(* Logix 5000 project; controller R21 vendor 1 type 14 code 96 rev 21.11; software revision 21.00; part 5 of 5 *)

ADD_ON_INSTRUCTION PSDNP3EventG40V03   (* revision 1.0, vendor ProSoft Technology Inc *)
VAR_IN_OUT
   EventBuffer : PSDNP3MasterEvent[1]; {required}
END_VAR
VAR_INPUT
   BufferSize : DINT; {required}
   CurrentBufferIndex : DINT; {required}
   Reset : BOOL; {required}
   OutstationNodeAddress : INT; {required}
   OutstationIPAddress0 : INT; {required}
   OutstationIPAddress1 : INT; {required}
   OutstationIPAddress2 : INT; {required}
   OutstationIPAddress3 : INT; {required}
END_VAR
VAR_IN_OUT
   DNP3StaticObject : PSDNP3AnalogOutputStatusRealFlag[1]; {required}
END_VAR
VAR_INPUT
   MaxtElementCount : DINT; {required}
END_VAR
VAR_OUTPUT
   EventsProcessed : DINT; {access Read Only, visible}
   LastElementIndex : DINT; {access Read Only, visible}
   LastValue : REAL; {access Read Only, visible}
   LastStatus : SINT; {access Read Only, visible}
   CurrentUnloadIndex : DINT; {access Read Only, visible}
END_VAR
VAR
   UnloadIndex : DINT; {access None}
   EnableInTemp : BOOL; {access None}
   InitialScan : BOOL; {access None}
   EntryValidForProcessing : BOOL; {access None}
   ElementIndex : DINT; {access None}
   NextIndex : DINT; {access None}
   ResetPulse : BOOL; {access None}
   ResetONS : BOOL; {access None}
END_VAR

ROUTINE Logic   (* ladder *)
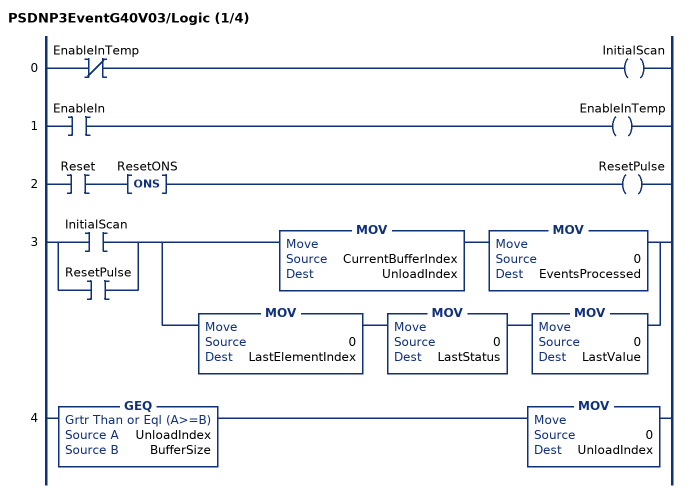
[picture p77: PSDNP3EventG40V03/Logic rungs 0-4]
   0: XIO(EnableInTemp)OTE(InitialScan);
   1: XIC(EnableIn)OTE(EnableInTemp);
   2: XIC(Reset)ONS(ResetONS)OTE(ResetPulse);
   3: [XIC(InitialScan) ,XIC(ResetPulse) ][MOV(CurrentBufferIndex,UnloadIndex) MOV(0,EventsProcessed) ,MOV(0,LastElementIndex) MOV(0,LastStatus) MOV(0,LastValue) ];
   4: GEQ(UnloadIndex,BufferSize)MOV(0,UnloadIndex);
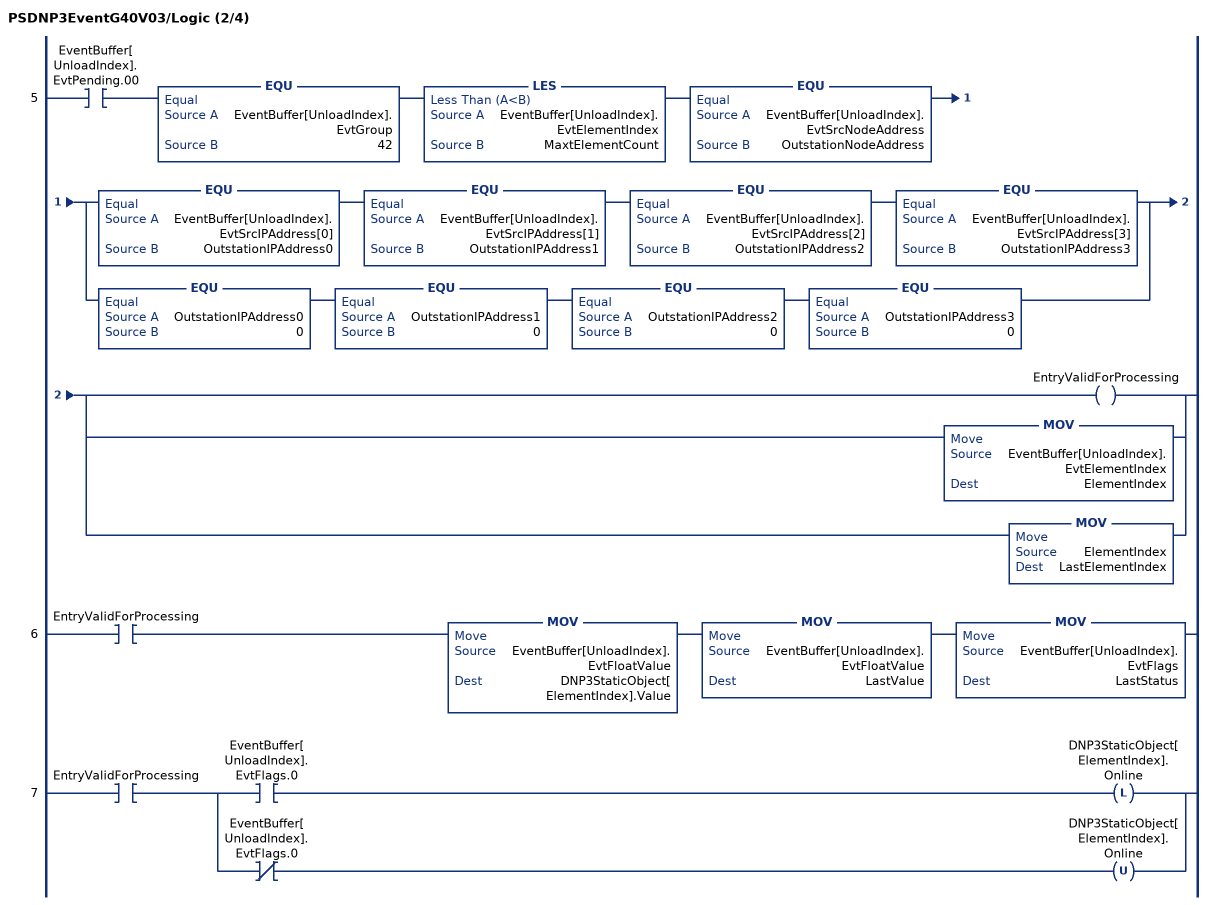
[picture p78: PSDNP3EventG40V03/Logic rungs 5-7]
   5: XIC(EventBuffer[UnloadIndex].EvtPending.00)EQU(EventBuffer[UnloadIndex].EvtGroup,42)LES(EventBuffer[UnloadIndex].EvtElementIndex,MaxtElementCount)EQU(EventBuffer[UnloadIndex].EvtSrcNodeAddress,OutstationNodeAddress)[EQU(EventBuffer[UnloadIndex].EvtSrcIPAddress[0],OutstationIPAddress0) EQU(EventBuffer[UnloadIndex].EvtSrcIPAddress[1],OutstationIPAddress1) EQU(EventBuffer[UnloadIndex].EvtSrcIPAddress[2],OutstationIPAddress2) EQU(EventBuffer[UnloadIndex].EvtSrcIPAddress[3],OutstationIPAddress3) ,EQU(OutstationIPAddress0,0) EQU(OutstationIPAddress1,0) EQU(OutstationIPAddress2,0) EQU(OutstationIPAddress3,0) ][OTE(EntryValidForProcessing) ,MOV(EventBuffer[UnloadIndex].EvtElementIndex,ElementIndex) ,MOV(ElementIndex,LastElementIndex) ];
   6: XIC(EntryValidForProcessing)MOV(EventBuffer[UnloadIndex].EvtFloatValue,DNP3StaticObject[ElementIndex].Value)MOV(EventBuffer[UnloadIndex].EvtFloatValue,LastValue)MOV(EventBuffer[UnloadIndex].EvtFlags,LastStatus);
   7: XIC(EntryValidForProcessing)[XIC(EventBuffer[UnloadIndex].EvtFlags.0) OTL(DNP3StaticObject[ElementIndex].Online) ,XIO(EventBuffer[UnloadIndex].EvtFlags.0) OTU(DNP3StaticObject[ElementIndex].Online) ];
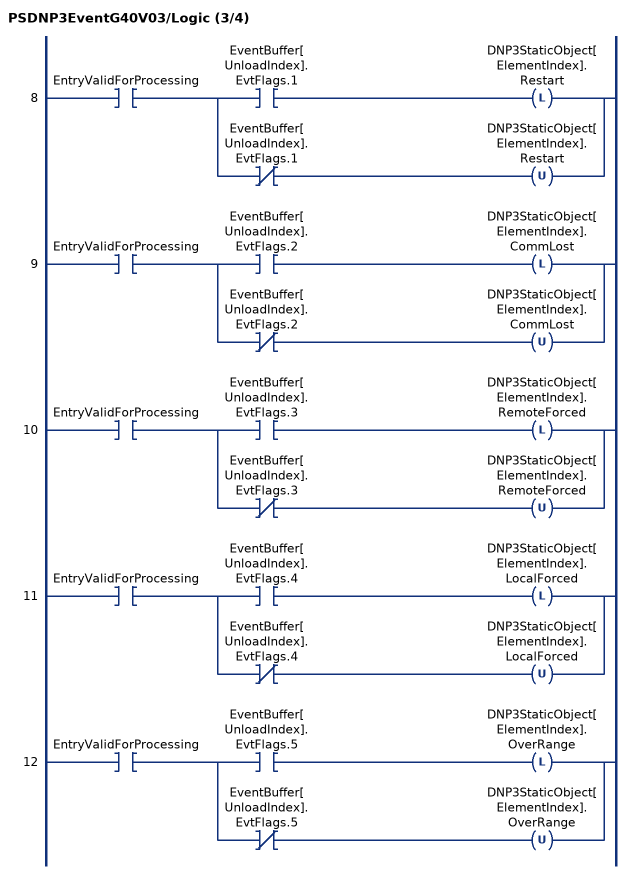
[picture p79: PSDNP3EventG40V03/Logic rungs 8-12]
   8: XIC(EntryValidForProcessing)[XIC(EventBuffer[UnloadIndex].EvtFlags.1) OTL(DNP3StaticObject[ElementIndex].Restart) ,XIO(EventBuffer[UnloadIndex].EvtFlags.1) OTU(DNP3StaticObject[ElementIndex].Restart) ];
   9: XIC(EntryValidForProcessing)[XIC(EventBuffer[UnloadIndex].EvtFlags.2) OTL(DNP3StaticObject[ElementIndex].CommLost) ,XIO(EventBuffer[UnloadIndex].EvtFlags.2) OTU(DNP3StaticObject[ElementIndex].CommLost) ];
   10: XIC(EntryValidForProcessing)[XIC(EventBuffer[UnloadIndex].EvtFlags.3) OTL(DNP3StaticObject[ElementIndex].RemoteForced) ,XIO(EventBuffer[UnloadIndex].EvtFlags.3) OTU(DNP3StaticObject[ElementIndex].RemoteForced) ];
   11: XIC(EntryValidForProcessing)[XIC(EventBuffer[UnloadIndex].EvtFlags.4) OTL(DNP3StaticObject[ElementIndex].LocalForced) ,XIO(EventBuffer[UnloadIndex].EvtFlags.4) OTU(DNP3StaticObject[ElementIndex].LocalForced) ];
   12: XIC(EntryValidForProcessing)[XIC(EventBuffer[UnloadIndex].EvtFlags.5) OTL(DNP3StaticObject[ElementIndex].OverRange) ,XIO(EventBuffer[UnloadIndex].EvtFlags.5) OTU(DNP3StaticObject[ElementIndex].OverRange) ];
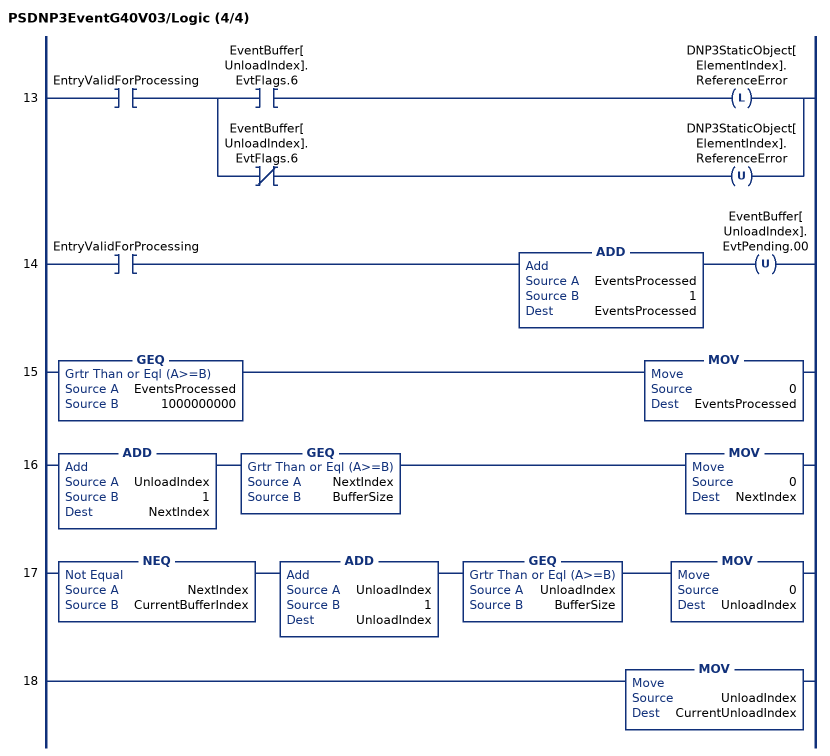
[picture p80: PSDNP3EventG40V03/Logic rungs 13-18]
   13: XIC(EntryValidForProcessing)[XIC(EventBuffer[UnloadIndex].EvtFlags.6) OTL(DNP3StaticObject[ElementIndex].ReferenceError) ,XIO(EventBuffer[UnloadIndex].EvtFlags.6) OTU(DNP3StaticObject[ElementIndex].ReferenceError) ];
   14: XIC(EntryValidForProcessing)ADD(EventsProcessed,1,EventsProcessed)OTU(EventBuffer[UnloadIndex].EvtPending.00);
   15: GEQ(EventsProcessed,1000000000)MOV(0,EventsProcessed);
   16: ADD(UnloadIndex,1,NextIndex)GEQ(NextIndex,BufferSize)MOV(0,NextIndex);
   17: NEQ(NextIndex,CurrentBufferIndex)ADD(UnloadIndex,1,UnloadIndex)GEQ(UnloadIndex,BufferSize)MOV(0,UnloadIndex);
   18: MOV(UnloadIndex,CurrentUnloadIndex);
END_ROUTINE
END_ADD_ON_INSTRUCTION

VAR_GLOBAL   (* controller tags *)
   DNP3G01V01 : PSDNP3BinaryInputPacked[10] := ([0].BinaryValues[0] := 9, [0].BinaryValues[1] := 1, [0].BinaryValues[2] := 1, [0].BinaryValues[3] := -64);
   DNP3G01V02 : PSDNP3BinaryInputWithFlag[100];
   DNP3G01V02_RBE : PSDNP3EventG01V02 := (BufferSize := 100, CurrentBufferIndex := 10, Reset := 1, OutstationNodeAddress := 2, MaxtElementCount := 10, EventsProcessed := 3, LastStatus := 81, CurrentUnloadIndex := 9);
   DNP3G03V01 : PSDNP3DoubleBinaryInputPacked[10];
   DNP3G03V02 : PSDNP3DoubleBinaryInputWithFlag[10] := ([0].Online := 1, [0].LocalForced := 1, [0].State0 := 1, [0].State1 := 1, [1].State1 := 1, [9].Online := 1, [9].CommLost := 1, [9].LocalForced := 1, [9].State0 := 1);
   DNP3G03V02_RBE : PSDNP3EventG03V02 := (BufferSize := 100, CurrentBufferIndex := 10, Reset := 1, OutstationNodeAddress := 2, MaxtElementCount := 10, EventsProcessed := 6, LastElementIndex := 1, LastValue := 2, CurrentUnloadIndex := 9);
   DNP3G10V0 : PSDNP3BinaryOutputWithFlag[10] := ([0].Online := 1, [0].CommLost := 1, [0].LocalForced := 1, [0].Reserved2 := 1, [2].Online := 1, [2].State := 1);
   DNP3G10V01 : PSDNP3BinaryOutputPacked[10];
   DNP3G10V02 : PSDNP3BinaryOutputWithFlag[10] := ([0].Online := 1, [0].LocalForced := 1, [0].Reserved2 := 1, [0].State := 1, [1].Online := 1, [1].Restart := 1, [9].Online := 1, [9].CommLost := 1, [9].LocalForced := 1);
   DNP3G10V02_RBE : PSDNP3EventG10V02 := (BufferSize := 100, CurrentBufferIndex := 10, Reset := 1, OutstationNodeAddress := 2, MaxtElementCount := 10, EventsProcessed := 5, LastValue := 1, LastStatus := 81, CurrentUnloadIndex := 9);
   DNP3G110V01 : STRING[5];
   DNP3G12V01 : PSDNP3CROB[10] := ([0].ControlCode := 4, [0].Count := 5, [0].OnTime := 200, [0].OffTime := 380, [3].RequestPending := 1, [3].ControlCode := 3, [3].Count := 1, [3].OnTime := 100, [3].OffTime := 100);
   DNP3G1V0 : PSDNP3BinaryInputWithFlag[10] := ([0].Online := 1, [0].LocalForced := 1, [0].State := 1, [1].Online := 1, [2].Online := 1, [2].Restart := 1, [2].CommLost := 1, [4].Online := 1, [4].Restart := 1, [4].CommLost := 1, [4].RemoteForced := 1, [4].LocalForced := 1, [5].State := 1, [7].State := 1, [8].State := 1, [9].State := 1);
   DNP3G20_Freeze : PSDNP3FreezeCmd[10];
   DNP3G20V0 : PSDNP3Counter32WithFlag[10];
   DNP3G20V01 : PSDNP3Counter32WithFlag[10];
   DNP3G20V01_RBE : PSDNP3EventG20V01 := (BufferSize := 100, CurrentBufferIndex := 10, Reset := 1, OutstationNodeAddress := 2, MaxtElementCount := 10, EventsProcessed := 2, LastValue := 17, LastStatus := 19, CurrentUnloadIndex := 9);
   DNP3G20V02 : PSDNP3Counter16WithFlag[10];
   DNP3G20V05 : DINT[10] := ([0] := 143, [1] := 144, [2] := 145, [3] := 146, [4] := 147, [5] := 148, [6] := 149, [7] := 150, [8] := 151, [9] := 3456);
   DNP3G20V06 : INT[10] := ([0] := 6, [1] := 154, [2] := 155, [3] := 156, [4] := 157, [5] := 158, [6] := 159, [7] := 160, [8] := 161, [9] := 3456);
   DNP3G21V0 : PSDNP3FrozenCounter32WithFlagTime[10];
   DNP3G21V01 : PSDNP3FrozenCounter32WithFlag[10] := ([0].LocalForced := 1, [0].Value := 88, [1].Online := 1, [1].Value := 324, [2].Restart := 1, [2].CommLost := 1, [2].Value := 100268, [9].Online := 1, [9].CommLost := 1, [9].LocalForced := 1, [9].Discontinuity := 1, [9].Value := 3456);
   DNP3G21V01_RBE : PSDNP3EventG21V01 := (BufferSize := 100, CurrentBufferIndex := 10, Reset := 1, OutstationNodeAddress := 2, MaxtElementCount := 10, EventsProcessed := 10, LastValue := 88, LastStatus := 16, CurrentUnloadIndex := 9);
   DNP3G21V02 : PSDNP3FrozenCounter16WithFlag[10] := ([0].Online := 1, [0].Value := 32000, [5].Restart := 1, [5].CommLost := 1, [5].Value := 31000, [9].Online := 1, [9].CommLost := 1, [9].LocalForced := 1, [9].Discontinuity := 1, [9].Value := 3456);
   DNP3G21V05 : PSDNP3FrozenCounter32WithFlagTime[100];
   DNP3G21V05_RBE : PSDNP3EventG21V05 := (BufferSize := 100, CurrentBufferIndex := 13, Reset := 1, OutstationNodeAddress := 2, MaxtElementCount := 10, EventsProcessed := 73, LastValue := 77, LastStatus := 16, CurrentUnloadIndex := 12);
   DNP3G21V06 : PSDNP3FrozenCounter16WithFlagTime[10] := ([0].Online := 1, [0].Value := 3, [9].Online := 1, [9].CommLost := 1, [9].LocalForced := 1, [9].Discontinuity := 1, [9].Value := 3456, [9].TimeOfOccurrence := 1484716130000200);
   DNP3G21V09 : DINT[10] := ([9] := 3456);
   DNP3G21V10 : INT[10] := ([0] := 6, [9] := 3456);
   DNP3G30_Freeze : PSDNP3FreezeCmd[10];
   DNP3G30V0 : PSDNP3AnalogInputVar0[10];
   DNP3G30V01 : PSDNP3AnalogInput32Flag[10];
   DNP3G30V02 : PSDNP3AnalogInput16Flag[10] := ([9].Online := 1, [9].Restart := 1, [9].CommLost := 1, [9].Value := 3456);
   DNP3G30V03 : DINT[10] := ([9] := 3456);
   DNP3G30V04 : INT[10] := ([9] := 3456);
   DNP3G30V05 : PSDNP3AnalogInputRealFlag[100];
   DNP3G30V05_RBE : PSDNP3EventG30V05 := (BufferSize := 100, CurrentBufferIndex := 10, Reset := 1, OutstationNodeAddress := 2, MaxtElementCount := 10, EventsProcessed := 2, LastValue := 345.0, LastStatus := 1, CurrentUnloadIndex := 9);
   DNP3G31V01 : PSDNP3FrozenAnalog32WithFlag[10];
   DNP3G31V02 : PSDNP3FrozenAnalog16WithFlag[10];
   DNP3G31V03 : PSDNP3FrozenAnalog32WithFlagTime[10];
   DNP3G31V04 : PSDNP3FrozenAnalog16WithFlagTime[10];
   DNP3G31V05 : DINT[10];
   DNP3G31V06 : INT[10];
   DNP3G31V07 : PSDNP3FrozenAnalogRealWithFlag[10];
   DNP3G3V0 : PSDNP3DoubleBinaryInputWithFlag[10];
   DNP3G40V0 : PSDNP3AnalogOutputVar0[10];
   DNP3G40V01 : PSDNP3AnalogOutputStatus32Flag[10] := ([0].Online := 1, [0].Value := 56, [9].Online := 1, [9].CommLost := 1, [9].LocalForced := 1, [9].ReferenceError := 1, [9].Value := 3456);
   DNP3G40V02 : PSDNP3AnalogOutputStatus16Flag[10] := ([0].Online := 1, [0].Value := 123, [9].Online := 1, [9].CommLost := 1, [9].LocalForced := 1, [9].ReferenceError := 1, [9].Value := 3456);
   DNP3G40V03 : PSDNP3AnalogOutputStatusRealFlag[10] := ([0].Online := 1, [0].Value := 66.0, [1].Online := 1, [1].Value := 760.0, [9].Online := 1, [9].CommLost := 1, [9].LocalForced := 1, [9].ReferenceError := 1, [9].Value := 71.25);
   DNP3G40V03_RBE : PSDNP3EventG40V03 := (BufferSize := 100, CurrentBufferIndex := 10, Reset := 1, OutstationNodeAddress := 2, MaxtElementCount := 10, EventsProcessed := 2, LastValue := 66.0, LastStatus := 1, CurrentUnloadIndex := 9);
   DNP3G41V01 : PSDNP3AnalogOutput32[10] := ([0].Value := 56, [7].RequestPending := 1, [7].Value := 77);
   DNP3G41V02 : PSDNP3AnalogOutput16[10] := ([0].Value := 123);
   DNP3G41V03 : PSDNP3AnalogOutputReal[10] := ([0].Value := 33.56);
   DNP3MasterEventBuffer : PSDNP3MasterEvent[100];
   DNP3MasterUnloadReset : BOOL := 1;
   DNP3Message : MESSAGE;
        MessageParameters(ServiceCode := 16#006a, LocalElement := DNP3MsgRequest, DestinationTag := DNP3MsgResponse, ...)
   DNP3MsgRequest : PSDNP3MsgRequest := (DestinationNode := 1, RequestDataSize := 5, IPAddress[0] := 192, IPAddress[1] := 168, IPAddress[2] := 1, IPAddress[3] := 210, Function := 1);
   DNP3MsgResponse : PSDNP3MsgResponse;
   DNPMessageTrigger : BOOL;
END_VAR

PROGRAM DNP3Events   (* main routine Main *)

ROUTINE FromOutstation_01   (* ladder *)
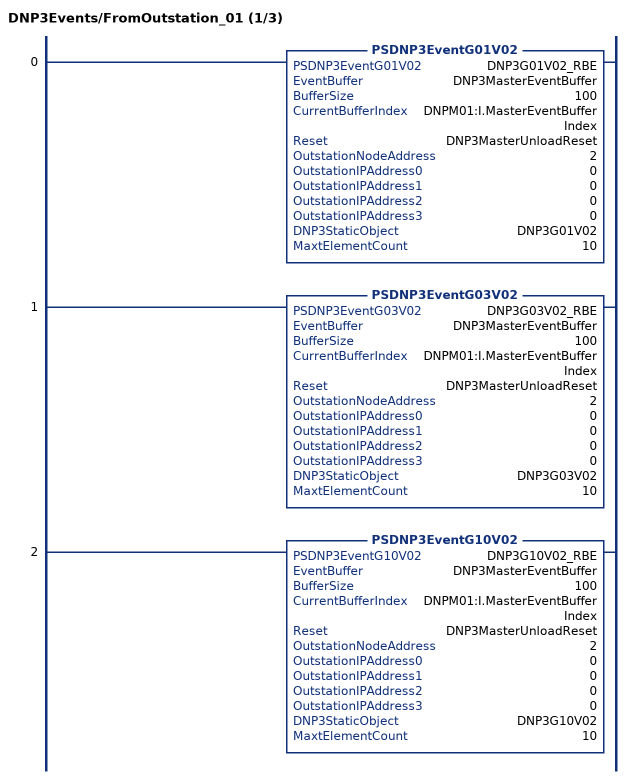
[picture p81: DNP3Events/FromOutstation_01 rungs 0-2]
   0: PSDNP3EventG01V02(DNP3G01V02_RBE,DNP3MasterEventBuffer,100,DNPM01:I.MasterEventBufferIndex,DNP3MasterUnloadReset,2,0,0,0,0,DNP3G01V02,10);
   1: PSDNP3EventG03V02(DNP3G03V02_RBE,DNP3MasterEventBuffer,100,DNPM01:I.MasterEventBufferIndex,DNP3MasterUnloadReset,2,0,0,0,0,DNP3G03V02,10);
   2: PSDNP3EventG10V02(DNP3G10V02_RBE,DNP3MasterEventBuffer,100,DNPM01:I.MasterEventBufferIndex,DNP3MasterUnloadReset,2,0,0,0,0,DNP3G10V02,10);
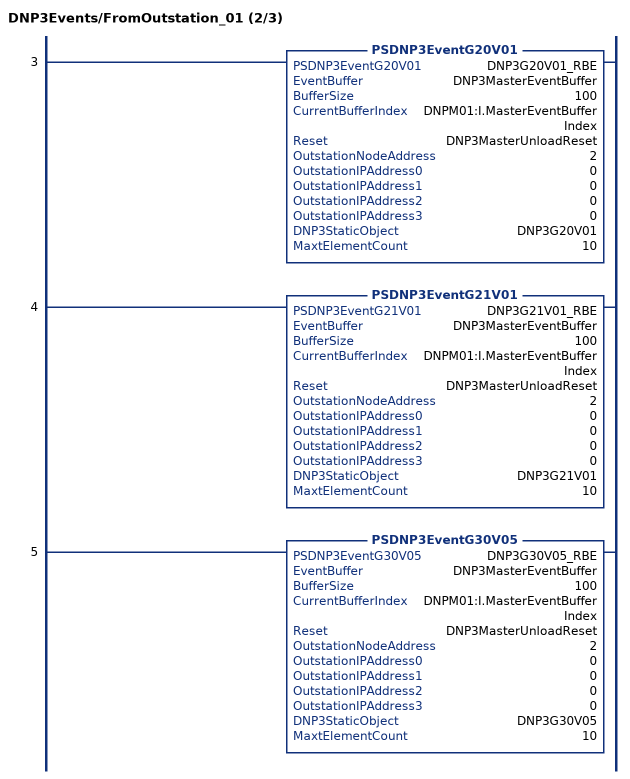
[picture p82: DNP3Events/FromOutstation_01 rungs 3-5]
   3: PSDNP3EventG20V01(DNP3G20V01_RBE,DNP3MasterEventBuffer,100,DNPM01:I.MasterEventBufferIndex,DNP3MasterUnloadReset,2,0,0,0,0,DNP3G20V01,10);
   4: PSDNP3EventG21V01(DNP3G21V01_RBE,DNP3MasterEventBuffer,100,DNPM01:I.MasterEventBufferIndex,DNP3MasterUnloadReset,2,0,0,0,0,DNP3G21V01,10);
   5: PSDNP3EventG30V05(DNP3G30V05_RBE,DNP3MasterEventBuffer,100,DNPM01:I.MasterEventBufferIndex,DNP3MasterUnloadReset,2,0,0,0,0,DNP3G30V05,10);
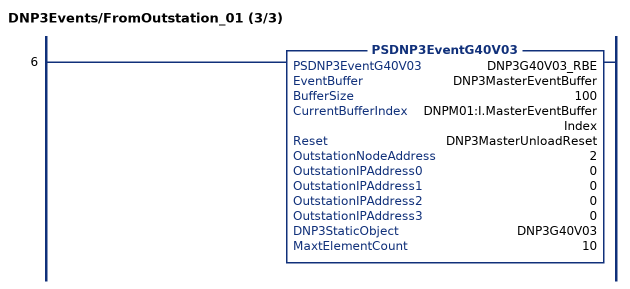
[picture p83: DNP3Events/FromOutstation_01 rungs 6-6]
   6: PSDNP3EventG40V03(DNP3G40V03_RBE,DNP3MasterEventBuffer,100,DNPM01:I.MasterEventBufferIndex,DNP3MasterUnloadReset,2,0,0,0,0,DNP3G40V03,10);
END_ROUTINE

ROUTINE Main   (* ladder *)
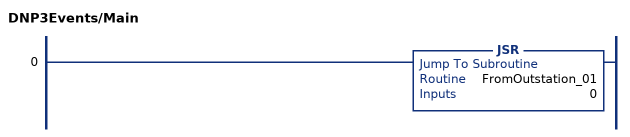
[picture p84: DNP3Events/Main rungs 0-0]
   0: JSR(FromOutstation_01,0);
END_ROUTINE
END_PROGRAM

PROGRAM MainProgram   (* main routine MainRoutine *)

ROUTINE DNP3Router   (* ladder *)
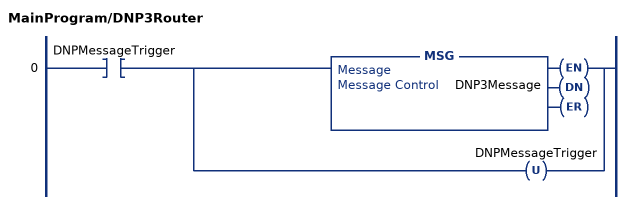
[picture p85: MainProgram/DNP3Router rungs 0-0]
   0: XIC(DNPMessageTrigger)[MSG(DNP3Message) ,OTU(DNPMessageTrigger) ];
END_ROUTINE

ROUTINE MainRoutine   (* ladder *)
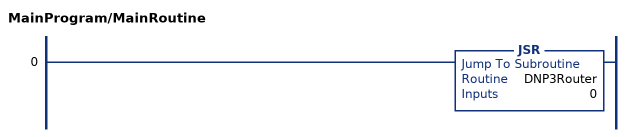
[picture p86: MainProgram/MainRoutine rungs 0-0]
   0: JSR(DNP3Router,0);
END_ROUTINE
END_PROGRAM
